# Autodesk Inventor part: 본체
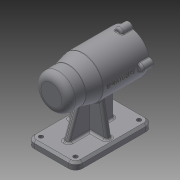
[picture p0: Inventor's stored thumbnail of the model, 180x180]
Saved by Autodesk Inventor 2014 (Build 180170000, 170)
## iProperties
Created: 2019-07
Part Number: 본체
Material: Generic
Document SubType Name: Modeling
Designer: kh
Density: 1 g/cm^3
Appearance: Default
Author: kh
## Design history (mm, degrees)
sketch "Sketch1"
  geometry: L1 (0, 0)-(112, 0); L2 (0, 0)-(0, 25); L3 (0, 25)-(25, 25); L4 (25, 25)-(45, 30); L5 (45, 30)-(112, 30); L6 (112, 30)-(112, 21); L7 (112, 21)-(97, 21); L8 (97, 21)-(97, 24); L9 (97, 24)-(43, 24); L10 (43, 24)-(43, 21); L11 (43, 21)-(31, 21); L12 (31, 21)-(31, 17.5); L13 (31, 17.5)-(13, 17.5); L14 (13, 17.5)-(13, 16); L15 (13, 16)-(9, 16); L16 (9, 16)-(9, 10.5); L17 (9, 10.5)-(6, 10.5); L18 (6, 10.5)-(6, 0)
  constraints: 36 end point, 8 parallel, 5 perpendicular, 2 horizontal, 1 collinear, 1 point on line, 1 vertical, 1 vertical alignment
  dimensions: "d0" = 112 distance of L1.start L1.end; "d1" = 50 diameter of L3 L1; "d2" = 21 diameter of L17 L1; "d3" = 32 diameter of L15 L1; "d4" = 35 diameter of L13 L1; "d5" = 42 diameter of L11 L1; "d6" = 48 diameter of L9 L1; "d7" = 42 diameter of L7 L1; "d8" = 25 distance of L2.end L3.end; "d9" = 45 distance from line of L4.end L2; "d10" = 60 diameter of L5 L1; "d11" = 3 distance of L16.end L17.end; "d12" = 4 distance of L14.end L15.end; "d13" = 18 distance of L12.end L13.end; "d14" = 12 distance of L10.end L11.end; "d15" = 54 distance of L8.end L9.end; "d16" = 15 distance of L6.end L7.end
revolve "Revolution1" sketch "Sketch1" stored, may be unused: angle "d17" = 90 deg
sketch "Sketch2"
  geometry: L1 (-35, -70)-(35, -70); L2 (35, -70)-(35, -80); L3 (35, -80)-(-35, -80); L4 (-35, -80)-(-35, -70); C1 r 25 at (0, 0) reference; 1 further point
  constraints: 8 end point, 2 parallel, 1 horizontal, 1 midpoint, 1 perpendicular, 1 vertical alignment
  dimensions: "d18" = 80 distance from line of L3 C1.centre; "d19" = 10 distance of L3.end L1.start; "d20" = 70 distance of L2.end L3.end
extrude "Extrusion1" join sketch "Sketch2" distance "d21" = 112; taper "d22" = 0 deg
fillet "Fillet1" dims "d23" = 10
workplane "Work Plane1"
sketch "Sketch3"
  geometry: L1 (26.67, 45.8)-(10, 0); L2 (77, 45.8)-(77, 0); L3 (26.67, 45.8)-(77, 45.8); L4 (10, 0)-(77, 0); L5 (-10, -10)-(-10, 0) reference; L6 (102, 0)-(102, -10) reference; L7 (0, 0)-(92, 0) reference; 1 further point
  constraints: 8 end point, 1 collinear, 1 horizontal, 1 perpendicular, 1 vertical
  dimensions: "d24" = 20 distance from line of L1.end L5; "d25" = 25 distance between parallel lines of L6 L2; "d26" = 110 deg angle of L7 L1; "d27" = 45.8 distance of L2.start L2.end
extrude "Extrusion2" join sketch "Sketch3" stored distance "d28" = 8; taper "d29" = 0 deg
workplane "Work Plane2"
sketch "Sketch4"
  geometry: L1 (-25, -70)-(25, -70) reference; L2 (-35, -80)-(-35, -70) reference; L3 (-19.654, -22.666)-(-28, -70); L4 (-35, -70)-(-25, -70) reference; L5 (0, -70)-(0, -53.293); L6 (19.654, -22.666)-(28, -70); 2 further points
  constraints: 6 end point, 2 symmetric about line, 1 midpoint, 1 perpendicular, 1 point on line, 2 other
  dimensions: "d31" = 7 distance of L3.end L2.end; "d32" = 100 deg angle of L4 L3
feature "Rib1" dims "d33" = 1, "d34" = 8, "d35" = 0, "d36" = 0, "d37" = 1, "d38" = 1
feature "Rib2" dims "d39" = 1, "d40" = 8, "d41" = 0, "d42" = 0, "d43" = 1, "d44" = 1
sketch "Sketch5"
  geometry: C1 r 6 at (0, 30); 1 further point
  constraints: 2 vertical alignment, 1 centre point, 1 other
  dimensions: "d46" = 6 radius of C1
extrude "Extrusion3" join sketch "Sketch5" distance "d47" = 16; taper "d48" = 0 deg
fillet "Fillet2" dims "d49" = 3
fillet "Fillet3" dims "d50" = 1
pattern_circular "Circular Pattern1" dims "d52" = 360 deg
fillet "Fillet4" dims "d56" = 3
fillet "Fillet5" dims "d57" = 0.3
fillet "Fillet6" dims "d58" = 3
chamfer "Chamfer1" distance "d59" = 1; stored, may be unused: second distance "d60" = 2, angle "d61" = 45 deg
fillet "Fillet7" dims "d62" = 3
chamfer "Chamfer2" distance "d63" = 3; stored, may be unused: second distance "d64" = 2, angle "d65" = 45 deg
fillet "Fillet8" dims "d66" = 3
fillet "Fillet9" dims "d67" = 3
sketch "Sketch7"
  geometry: C1 r 3 at (0, 57); C2 r 3 at (0, 7); C3 r 3 at (92, 57); C4 r 3 at (92, 7); A1 r 7 centre (0, 7) between (-7, 7) and (0, 0) reference; A2 r 7 centre (92, 7) between (92, 0) and (99, 7) reference; A3 r 7 centre (92, 57) between (99, 57) and (92, 64) reference; A4 r 7 centre (0, 57) between (0, 64) and (-7, 57) reference; 1 further point
  constraints: 4 centre point, 4 coincident, 3 equal radius
  dimensions: "d68" = 6 diameter of C1
extrude "Extrusion5" cut sketch "Sketch7" stored distance "d69" = 0; taper "d70" = 0 deg
fillet "Fillet10" dims "d71" = 10
fillet "Fillet11" dims "d72" = 3
workplane "Work Plane4"
sketch "Sketch8"
  geometry: L1 (102, 86.771)-(102, 109.226) reference; 2 further points
  constraints: 1 horizontal alignment, 1 other
  dimensions: "d74" = 42 distance from line of point (60, 80) L1
emboss "Emboss1" sketch "Sketch8" dims "d0" = 112, "d1" = 50, "d2" = 21, "d3" = 32, "d4" = 35, "d5" = 42, "d6" = 48, "d7" = 42, "d8" = 25, "d9" = 45, "d10" = 60, "d11" = 3, "d12" = 4, "d13" = 18, "d14" = 12, "d15" = 54, "d16" = 15, "d75" = 0.5, "d76" = 0
body "Solid1"
other parameters: "d73" = 16.25
